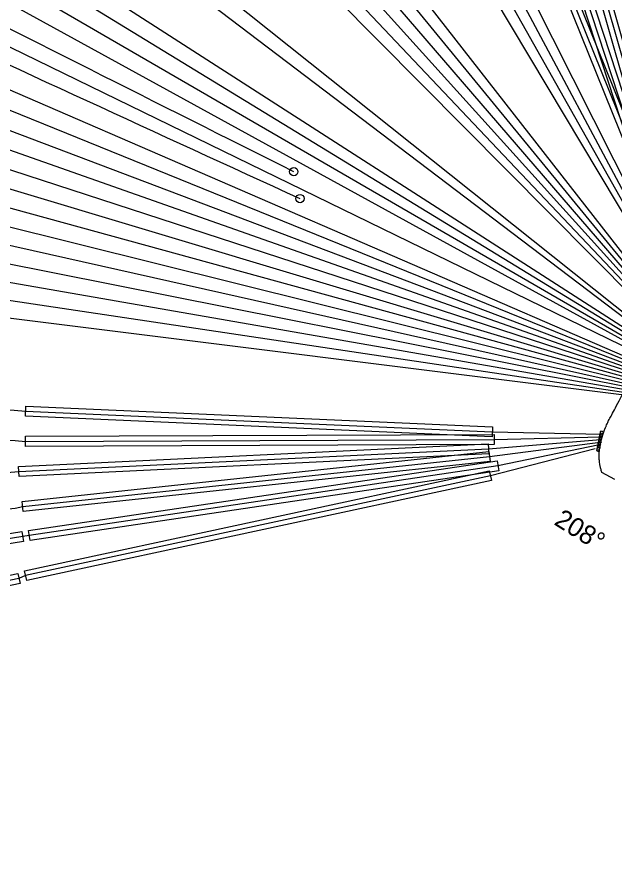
# Model space of a CAD drawing. Extents: x 387828 to 391861, y 7650362 to 7652502.
# Drawn here: x 390545 to 391179, y 7650362 to 7651275 of the extents above; entities that cross this region are included whole.
import ezdxf

# ---------------------------------------------------------------- set-up
doc = ezdxf.new("R2010")
doc.units = 0
for name, color, linetype in [('Plataforma fixa FPSO', 7, 'Continuous'), ('Plataforma movel NS', 7, 'Continuous'), ('Sistemas de ancoragem', 7, 'Continuous'), ('TDP', 7, 'Continuous'), ('Texto das plataformas fixas', 7, 'Continuous'), ('Variacoes de flexivel', 7, 'Continuous')]:
    doc.layers.add(name, color=color, linetype=linetype)

msp = doc.modelspace()

# ---------------------------------------------------------------- linework, layer by layer
at = {"layer": 'Plataforma fixa FPSO'}
msp.add_line((391178.54, 7650784.71), (391164.88, 7650791.97), dxfattribs=at)
msp.add_lwpolyline([(391166.67, 7650834.54), (391165.05, 7650835.4), (391163.25, 7650835.75), (391159.29, 7650815.34), (391162.11, 7650813.84)], dxfattribs=at)
for centre, radius in [((391163.45, 7650827.05), 1), ((391163.99, 7650829.82), 1), ((391164.52, 7650832.6), 1.01), ((391161.82, 7650818.69), 0.97), ((391162.36, 7650821.46), 0.97), ((391162.9, 7650824.26), 1.01), ((391161.28, 7650815.91), 0.303)]:
    msp.add_circle(centre, radius, dxfattribs=at)
for points, degree in [([(391171.68, 7650846.56), (391171.68, 7650846.56), (391262.97, 7651018.27), (391262.97, 7651018.27)], 2), ([(391167.57, 7650836.94), (391167.57, 7650836.94), (391168.15, 7650838.34), (391168.15, 7650838.34), (391168.15, 7650838.34), (391168.15, 7650838.34), (391168.72, 7650839.7), (391168.72, 7650839.7), (391168.72, 7650839.7), (391168.72, 7650839.7), (391169.33, 7650841.08), (391169.33, 7650841.08), (391169.33, 7650841.08), (391169.33, 7650841.08), (391171.68, 7650846.56), (391171.68, 7650846.56)], 3), ([(391162.73, 7650800.37), (391162.73, 7650800.37), (391162.36, 7650803.33), (391162.36, 7650803.33), (391162.36, 7650803.33), (391162.36, 7650803.33), (391162.08, 7650806.32), (391162.08, 7650806.32), (391162.08, 7650806.32), (391162.08, 7650806.32), (391162.07, 7650807.06), (391162.07, 7650807.06), (391162.07, 7650807.06), (391162.07, 7650807.06), (391162.01, 7650807.78), (391162.01, 7650807.78), (391162.01, 7650807.78), (391162.01, 7650807.78), (391161.96, 7650808.53), (391161.96, 7650808.53), (391161.96, 7650808.53), (391161.96, 7650808.53), (391161.96, 7650809.3), (391161.96, 7650809.3), (391161.96, 7650809.3), (391161.96, 7650809.3), (391161.94, 7650810.78), (391161.94, 7650810.78), (391161.94, 7650810.78), (391161.94, 7650810.78), (391162.04, 7650813.03), (391162.04, 7650813.03), (391162.04, 7650813.03), (391162.04, 7650813.03), (391162.24, 7650815.24), (391162.24, 7650815.24), (391162.24, 7650815.24), (391162.24, 7650815.24), (391162.45, 7650816.71), (391162.45, 7650816.71), (391162.45, 7650816.71), (391162.45, 7650816.71), (391162.65, 7650818.22), (391162.65, 7650818.22), (391162.65, 7650818.22), (391162.65, 7650818.22), (391162.9, 7650819.68), (391162.9, 7650819.68), (391162.9, 7650819.68), (391162.9, 7650819.68), (391163.16, 7650821.16), (391163.16, 7650821.16), (391163.16, 7650821.16), (391163.16, 7650821.16), (391163.4, 7650822.61), (391163.4, 7650822.61), (391163.4, 7650822.61), (391163.4, 7650822.61), (391163.73, 7650824.06), (391163.73, 7650824.06), (391163.73, 7650824.06), (391163.73, 7650824.06), (391164.07, 7650825.54), (391164.07, 7650825.54), (391164.07, 7650825.54), (391164.07, 7650825.54), (391164.42, 7650826.98), (391164.42, 7650826.98), (391164.42, 7650826.98), (391164.42, 7650826.98), (391164.8, 7650828.44), (391164.8, 7650828.44), (391164.8, 7650828.44), (391164.8, 7650828.44), (391165.23, 7650829.87), (391165.23, 7650829.87), (391165.23, 7650829.87), (391165.23, 7650829.87), (391165.62, 7650831.29), (391165.62, 7650831.29), (391165.62, 7650831.29), (391165.62, 7650831.29), (391166.06, 7650832.72), (391166.06, 7650832.72), (391166.06, 7650832.72), (391166.06, 7650832.72), (391166.32, 7650833.43), (391166.32, 7650833.43), (391166.32, 7650833.43), (391166.32, 7650833.43), (391166.53, 7650834.13), (391166.53, 7650834.13), (391166.53, 7650834.13), (391166.53, 7650834.13), (391167.04, 7650835.56), (391167.04, 7650835.56), (391167.04, 7650835.56), (391167.04, 7650835.56), (391167.57, 7650836.94), (391167.57, 7650836.94)], 3), ([(391163.25, 7650835.75), (391163.25, 7650835.75), (391159.29, 7650815.34), (391159.29, 7650815.34)], 2), ([(391163.15, 7650798.33), (391163.15, 7650798.33), (391163.03, 7650798.8), (391163.03, 7650798.8), (391163.03, 7650798.8), (391163.03, 7650798.8), (391162.73, 7650800.37), (391162.73, 7650800.37)], 3), ([(391164.88, 7650791.97), (391164.88, 7650791.97), (391163.7, 7650796.09), (391163.7, 7650796.09), (391163.7, 7650796.09), (391163.7, 7650796.09), (391163.55, 7650796.65), (391163.55, 7650796.65), (391163.55, 7650796.65), (391163.55, 7650796.65), (391163.15, 7650798.33), (391163.15, 7650798.33)], 3)]:
    msp.add_open_spline(points, degree=degree, dxfattribs=at)
at = {"layer": 'Plataforma movel NS'}
for points in [[(390838, 7651111), (390406, 7651329), (390236.74, 7651416.77), (390068.91, 7651506.95), (389901.13, 7651597.91), (389732, 7651688), (389686.65, 7651709.26), (389663.37, 7651717.72), (389640, 7651724), (389627, 7651721), (389601.83, 7651708.14), (389578.19, 7651693.06), (389554.94, 7651677.96), (389531, 7651665), (389516.99, 7651661.85), (389501.81, 7651661.8), (389486.72, 7651661.35), (389473, 7651657), (389466.29, 7651649.75), (389462.15, 7651639.97), (389458.19, 7651629.95), (389452, 7651622), (389428.63, 7651606.36), (389404, 7651593), (389391.69, 7651589.81), (389378.34, 7651588.93), (389365.58, 7651586.58), (389359.91, 7651583.68), (389355, 7651579), (389349.38, 7651563.31), (389351.67, 7651546.52), (389355.87, 7651529.46), (389356, 7651513), (389328.76, 7651418.65), (389297.66, 7651324.72), (389268.47, 7651230.19), (389247, 7651134), (389246, 7651126), (389245, 7651099), (389244, 7651076), (389217.18, 7650362.31)], [(389245.88, 7650362.31), (389259.92, 7650703.97), (389269.96, 7651118.43), (389270.32, 7651123.69), (389290.32, 7651232.37), (389322.14, 7651338.27), (389360.95, 7651442.8), (389401.94, 7651547.36), (389405.41, 7651553.7), (389415.33, 7651559.44), (389599.08, 7651672.59), (389610.31, 7651677.5), (389616.53, 7651676.06), (389618.8, 7651670.56), (389682.04, 7651603.58), (389684.55, 7651602.38), (389697.94, 7651600.47), (389872.16, 7651525.1), (390045.93, 7651448.64), (390391.79, 7651291.99), (390844.64, 7651082.52)]]:
    msp.add_spline(points, degree=3, dxfattribs=at)
at = {"layer": 'Sistemas de ancoragem'}
for points in [[(390636.14, 7652502.5), (390707.54, 7652342.09), (390763.54, 7652210.09), (391021.54, 7651573.09), (391024.54, 7651564.09), (391205.54, 7651115.09), (391263.24, 7651023)], [(390736.21, 7652502.5), (390775.54, 7652403.09), (390826.54, 7652245.09), (391048.54, 7651597.09), (391054.54, 7651581.09), (391210.54, 7651105.09), (391264.75, 7651025.8)], [(390813.84, 7652502.5), (390823.54, 7652472.09), (390881.54, 7652276.09), (391072.54, 7651618.09), (391078.54, 7651608.09), (391215.54, 7651130.09), (391266.24, 7651028.6)], [(389620.54, 7650915.09), (389693.54, 7650910.09), (389851.54, 7650894.09), (390541.54, 7650858.09), (390553.54, 7650857.09), (391048.54, 7650835.09), (391164.52, 7650832.6)], [(389610.54, 7650832.09), (389684.54, 7650831.09), (389842.54, 7650829.09), (390542.54, 7650826.09), (390553.54, 7650825.09), (391050.54, 7650827.09), (391163.99, 7650829.82)], [(389615.54, 7650750.09), (389668.54, 7650752.09), (389843.54, 7650755.09), (390533.54, 7650792.09), (390546.54, 7650793.09), (391044.54, 7650817.09), (391163.45, 7650827.05)], [(389620.54, 7650664.09), (389665.54, 7650668.09), (389844.54, 7650682.09), (390542.54, 7650754.09), (390550.54, 7650756.09), (391045.54, 7650809.09), (391162.9, 7650824.26)], [(391162.36, 7650821.46), (391054.54, 7650799.09), (390557.54, 7650725.09), (390550.54, 7650724.09), (389857.54, 7650613.09), (389712.54, 7650595.09), (389627.54, 7650584.09)], [(391157.81, 7650817.28), (391046.53, 7650788.68), (390553.53, 7650682.68), (390546.53, 7650679.68), (389859.53, 7650537.68), (389709.53, 7650509.68), (389646.53, 7650502.68)]]:
    msp.add_lwpolyline(points, dxfattribs=at)
for points in [[(391210.4, 7651128.54), (391073.4, 7651606.54), (391083.69, 7651609.63), (391220.69, 7651131.63)], [(391205.46, 7651103.35), (391049.46, 7651579.35), (391059.63, 7651582.82), (391215.63, 7651106.82)], [(391200.59, 7651113.02), (391019.59, 7651562.02), (391029.5, 7651566.16), (391210.5, 7651117.16)], [(391048.37, 7650829.72), (390553.37, 7650851.72), (390553.71, 7650862.46), (391048.71, 7650840.46)], [(391050.63, 7650821.72), (390553.63, 7650819.71), (390553.45, 7650830.46), (391050.45, 7650832.46)], [(391044.87, 7650811.72), (390546.87, 7650787.72), (390546.22, 7650798.45), (391044.22, 7650822.45)], [(391046.18, 7650803.75), (390551.18, 7650750.75), (390549.9, 7650761.42), (391044.9, 7650814.42)], [(391055.4, 7650793.78), (390558.4, 7650719.78), (390556.68, 7650730.39), (391053.69, 7650804.39)], [(391047.73, 7650783.44), (390554.73, 7650677.44), (390552.34, 7650687.91), (391045.34, 7650793.91)], [(390551.46, 7650718.79), (389858.46, 7650607.79), (389856.63, 7650618.38), (390549.63, 7650729.38)], [(390547.69, 7650674.43), (389860.69, 7650532.43), (389858.38, 7650542.92), (390545.38, 7650684.92)]]:
    msp.add_lwpolyline(points, close=True, dxfattribs=at)
at = {"layer": 'TDP'}
for centre in [(390838, 7651111), (390844.65, 7651082.52)]:
    msp.add_circle(centre, 4.41, dxfattribs=at)
at = {"layer": 'Variacoes de flexivel'}
for p, q in [((391277.72, 7650924.07), (390842.74, 7651790.4)), ((391276.87, 7650922.46), (390821.17, 7651778)), ((391276.04, 7650920.88), (390800.38, 7651765.41)), ((391275.19, 7650919.28), (390778.96, 7651751.8)), ((391272.64, 7650914.49), (390681.51, 7651671.61)), ((391271.8, 7650912.94), (390662.07, 7651656.53)), ((391270.96, 7650911.31), (390643.07, 7651641.01)), ((391270.09, 7650909.68), (390624.49, 7651625.02)), ((391269.26, 7650908.05), (390606.35, 7651608.59)), ((391268.41, 7650906.51), (390588.65, 7651591.74)), ((390586.11, 7651441.11), (391264.99, 7650900.05)), ((390572.88, 7651423.52), (391264.14, 7650898.49)), ((391263.31, 7650896.92), (390449.5, 7651420.43)), ((391262.44, 7650895.31), (390436.73, 7651399.75)), ((390424.38, 7651378.8), (391261.59, 7650893.72)), ((390412.5, 7651357.58), (391260.76, 7650892.11)), ((391259.9, 7650890.52), (390396.78, 7651311.12)), ((390369.45, 7651270.24), (391257.37, 7650885.72)), ((390360, 7651247.74), (391256.52, 7650884.12)), ((390350.9, 7651225.07), (391255.66, 7650882.54)), ((391254.82, 7650880.94), (390342.29, 7651202.16)), ((391253.95, 7650879.33), (390334.17, 7651179.02)), ((390326.53, 7651155.67), (391253.12, 7650877.73)), ((390319.4, 7651132.11), (391252.27, 7650876.15)), ((390312.77, 7651108.33), (391251.41, 7650874.52)), ((390306.65, 7651084.36), (391250.58, 7650872.94)), ((390301.05, 7651060.18), (391249.71, 7650871.34)), ((390295.96, 7651035.82), (391248.87, 7650869.8)), ((390291.42, 7651011.26), (391248.01, 7650868.15)), ((391247.16, 7650866.52), (390287.41, 7650986.52))]:
    msp.add_line(p, q, dxfattribs=at)

# ---------------------------------------------------------------- texts
at = {"layer": 'Texto das plataformas fixas'}
msp.add_text('208°', height=20, rotation=328, dxfattribs=at).set_placement((391113.07, 7650737.49))

doc.saveas('drawing.dxf')
